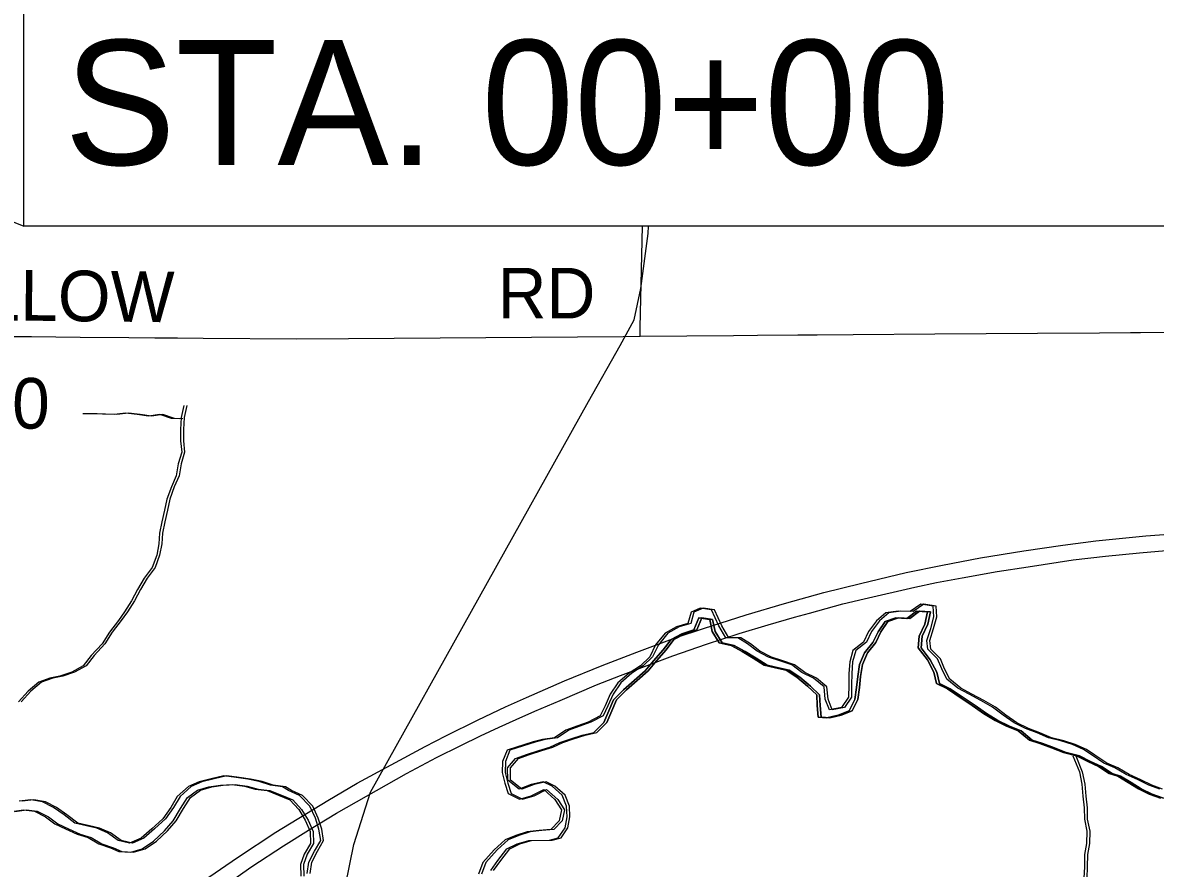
# Model space of a CAD drawing. Extents: x 0 to 34, y 0 to 22.
# Drawn here: x 17.627 to 18.899, y 3.831 to 4.78 of the extents above; entities that cross this region are included whole.
import ezdxf

# ---------------------------------------------------------------- set-up
doc = ezdxf.new("R2010")
doc.units = 0
for name, color, linetype in [('GM_X_County_Road', 7, 'Continuous'), ('GM_X_County_Road_Text', 7, 'Continuous'), ('GM_X_Interstate_Route', 7, 'Continuous'), ('GM_X_Minor_River', 7, 'Continuous'), ('GM_X_Rail_Line', 7, 'Continuous'), ('GM_X_Township_Road', 7, 'Continuous'), ('SH_Text', 7, 'Continuous')]:
    doc.layers.add(name, color=color, linetype=linetype)

msp = doc.modelspace()

# ---------------------------------------------------------------- linework, layer by layer
at = {"layer": 'GM_X_County_Road'}
msp.add_lwpolyline([(17.6039, 4.4277), (17.6373, 4.4274), (17.6921, 4.4268), (17.7464, 4.4263), (17.7757, 4.426), (17.8013, 4.4259), (17.83, 4.4257), (17.935, 4.425), (17.9932, 4.4255), (18.1474, 4.4264), (18.3016, 4.4276), (18.3206, 4.4278), (18.4254, 4.4287), (18.4524, 4.4289), (18.4976, 4.4293), (18.5193, 4.4295), (18.5599, 4.4298), (18.6513, 4.4304), (18.7668, 4.4313), (18.8363, 4.4318), (18.8711, 4.432), (18.8824, 4.4321), (19.0043, 4.433)], dxfattribs=at)
at = {"layer": 'GM_X_Interstate_Route'}
for points in [[(17.8303, 3.8168), (17.8684, 3.8428), (17.9116, 3.8711), (17.9699, 3.9067), (18.0029, 3.9261), (18.0792, 3.9676), (18.1025, 3.9795), (18.1387, 3.9975), (18.1696, 4.012), (18.1932, 4.0225), (18.2357, 4.041), (18.2779, 4.0583), (18.3169, 4.0734), (18.3599, 4.0892), (18.3916, 4.0999), (18.4397, 4.1153), (18.4825, 4.128), (18.5267, 4.1402), (18.568, 4.1504), (18.6194, 4.1627), (18.6599, 4.1711), (18.7026, 4.1791), (18.7512, 4.1872), (18.795, 4.1935), (18.832, 4.1982), (18.8883, 4.2037), (18.9594, 4.209)], [(17.8516, 3.8096), (17.8848, 3.8329), (17.9202, 3.8561), (17.9482, 3.8736), (17.9797, 3.8925), (18.0584, 3.937), (18.092, 3.9549), (18.1194, 3.9686), (18.1413, 3.9794), (18.1622, 3.9892), (18.1815, 3.9977), (18.2023, 4.0072), (18.2309, 4.0192), (18.2715, 4.0365), (18.2984, 4.0471), (18.3313, 4.0593), (18.3572, 4.0691), (18.3952, 4.0822), (18.4317, 4.0941), (18.4644, 4.1039), (18.4937, 4.1126), (18.5106, 4.1171), (18.5483, 4.1274), (18.572, 4.1332), (18.6289, 4.1463), (18.6534, 4.1514), (18.6821, 4.1568), (18.7215, 4.1638), (18.7562, 4.1692), (18.8068, 4.1769), (18.8432, 4.181), (18.8813, 4.1847), (18.9196, 4.1882)]]:
    msp.add_lwpolyline(points, dxfattribs=at)
at = {"layer": 'GM_X_Minor_River'}
for points in [[(17.8083, 4.3502), (17.8055, 4.3365), (17.8045, 4.3232), (17.8047, 4.3103), (17.806, 4.2978), (17.802, 4.2848), (17.7999, 4.2711), (17.7943, 4.2589), (17.7892, 4.2451), (17.7867, 4.2325), (17.7838, 4.2196), (17.781, 4.207), (17.7804, 4.1948), (17.7779, 4.1823), (17.7727, 4.1685), (17.7638, 4.1563), (17.7564, 4.1436), (17.7497, 4.131), (17.7419, 4.1187), (17.7348, 4.1088), (17.7247, 4.0957), (17.7166, 4.0827), (17.7042, 4.0696), (17.6953, 4.0581), (17.6825, 4.0507), (17.6692, 4.0464), (17.6579, 4.044), (17.6454, 4.0396), (17.6334, 4.0296), (17.6226, 4.0177)], [(17.8116, 4.3502), (17.8087, 4.3365), (17.8078, 4.3232), (17.8079, 4.3103), (17.8092, 4.2978), (17.8052, 4.2848), (17.8031, 4.2711), (17.7976, 4.2589), (17.7925, 4.2451), (17.79, 4.2325), (17.7871, 4.2196), (17.7842, 4.207), (17.7836, 4.1948), (17.7811, 4.1823), (17.776, 4.1685), (17.767, 4.1563), (17.7596, 4.1436), (17.753, 4.131), (17.7452, 4.1187), (17.7381, 4.1088), (17.728, 4.0957), (17.7198, 4.0827), (17.7075, 4.0696), (17.6985, 4.0581), (17.6857, 4.0507), (17.6725, 4.0464), (17.6612, 4.044), (17.6487, 4.0396), (17.6367, 4.0296), (17.6259, 4.0177)], [(17.804, 4.3353), (17.7945, 4.3356), (17.7815, 4.34), (17.7687, 4.3383), (17.7561, 4.3401), (17.7429, 4.3414), (17.73, 4.3401), (17.7171, 4.3403), (17.7076, 4.3406), (17.6951, 4.3408)], [(17.8072, 4.3353), (17.7978, 4.3356), (17.7848, 4.34), (17.7719, 4.3383), (17.7594, 4.3401), (17.7461, 4.3414), (17.7332, 4.3401), (17.7203, 4.3403), (17.7109, 4.3406), (17.6984, 4.3408)], [(18.9039, 3.9194), (18.8917, 3.9242), (18.8795, 3.9301), (18.8661, 3.936), (18.8535, 3.9435), (18.8413, 3.9486), (18.8279, 3.9576), (18.8184, 3.9639), (18.8058, 3.9695), (18.7928, 3.9738), (18.7791, 3.9771), (18.7662, 3.9826), (18.7532, 3.9878), (18.7403, 3.9941), (18.728, 4.0026), (18.7161, 4.0116), (18.7032, 4.019), (18.6898, 4.0261), (18.6772, 4.0328), (18.6649, 4.0429), (18.6591, 4.0546), (18.6544, 4.0659), (18.6437, 4.0768), (18.6424, 4.0863), (18.6468, 4.1), (18.6504, 4.113), (18.6495, 4.1251), (18.6358, 4.1272), (18.6238, 4.1191), (18.6101, 4.1193), (18.5965, 4.1176), (18.586, 4.1083), (18.5771, 4.0964), (18.5715, 4.0846), (18.5595, 4.0753), (18.5559, 4.0624), (18.5549, 4.0494), (18.5547, 4.0365), (18.5545, 4.0228), (18.5467, 4.0113), (18.5331, 4.0085), (18.5283, 4.0206), (18.527, 4.0343), (18.5152, 4.044), (18.5022, 4.0503), (18.4907, 4.0592), (18.4774, 4.0636), (18.4648, 4.0676), (18.4518, 4.0743), (18.4411, 4.0825), (18.4304, 4.0892), (18.4168, 4.0894), (18.409, 4.103), (18.4008, 4.1208), (18.3879, 4.1225), (18.3777, 4.1182), (18.3741, 4.1056), (18.3613, 4.1016), (18.3485, 4.0946), (18.338, 4.0816), (18.3313, 4.0682), (18.3209, 4.0578), (18.3081, 4.0497), (18.2957, 4.0389)], [(18.9039, 3.9194), (18.8917, 3.9242), (18.8795, 3.9301), (18.8661, 3.936), (18.8535, 3.9435), (18.8413, 3.9486), (18.8279, 3.9576), (18.8184, 3.9639), (18.8058, 3.9695), (18.7928, 3.9738), (18.7791, 3.9771), (18.7662, 3.9826), (18.7532, 3.9878), (18.7403, 3.9941), (18.728, 4.0026), (18.7161, 4.0116), (18.7032, 4.019), (18.6898, 4.0261), (18.6772, 4.0328), (18.6649, 4.0429), (18.6591, 4.0546), (18.6544, 4.0659), (18.6437, 4.0768), (18.6424, 4.0863), (18.6468, 4.1), (18.6504, 4.113), (18.6495, 4.1251), (18.6358, 4.1272), (18.6238, 4.1191), (18.6101, 4.1193), (18.5965, 4.1176), (18.586, 4.1083), (18.5771, 4.0964), (18.5715, 4.0846), (18.5595, 4.0753), (18.5559, 4.0624), (18.5549, 4.0494), (18.5547, 4.0365), (18.5545, 4.0228), (18.5467, 4.0113), (18.5331, 4.0085), (18.5283, 4.0206), (18.527, 4.0343), (18.5152, 4.044), (18.5022, 4.0503), (18.4907, 4.0592), (18.4774, 4.0636), (18.4648, 4.0676), (18.4518, 4.0743), (18.4411, 4.0825), (18.4304, 4.0892), (18.4168, 4.0894), (18.409, 4.103), (18.4008, 4.1208), (18.3879, 4.1225), (18.3777, 4.1182), (18.3741, 4.1056), (18.3613, 4.1016), (18.3485, 4.0946), (18.338, 4.0816), (18.3313, 4.0682), (18.3209, 4.0578), (18.3081, 4.0497), (18.2957, 4.0389)], [(18.9071, 3.9194), (18.8949, 3.9242), (18.8827, 3.9301), (18.8694, 3.936), (18.8568, 3.9435), (18.8446, 3.9486), (18.8312, 3.9576), (18.8216, 3.9639), (18.809, 3.9695), (18.7961, 3.9738), (18.7824, 3.9771), (18.7694, 3.9826), (18.7565, 3.9878), (18.7435, 3.9941), (18.7313, 4.0026), (18.7194, 4.0116), (18.7064, 4.019), (18.6931, 4.0261), (18.6805, 4.0328), (18.6682, 4.0429), (18.6624, 4.0546), (18.6577, 4.0659), (18.6469, 4.0768), (18.6457, 4.0863), (18.65, 4.1), (18.6537, 4.113), (18.6528, 4.1251), (18.6391, 4.1272), (18.6271, 4.1191), (18.6134, 4.1193), (18.5998, 4.1176), (18.5893, 4.1083), (18.5803, 4.0964), (18.5748, 4.0846), (18.5628, 4.0753), (18.5591, 4.0624), (18.5582, 4.0494), (18.558, 4.0365), (18.5578, 4.0228), (18.5499, 4.0113), (18.5363, 4.0085), (18.5316, 4.0206), (18.5303, 4.0343), (18.5184, 4.044), (18.5055, 4.0503), (18.494, 4.0592), (18.4806, 4.0636), (18.4681, 4.0676), (18.4551, 4.0743), (18.4444, 4.0825), (18.4337, 4.0892), (18.42, 4.0894), (18.4123, 4.103), (18.4041, 4.1208), (18.3912, 4.1225), (18.381, 4.1182), (18.3774, 4.1056), (18.3645, 4.1016), (18.3517, 4.0946), (18.3413, 4.0816), (18.3346, 4.0682), (18.3241, 4.0578), (18.3113, 4.0497), (18.299, 4.0389)], [(18.9071, 3.9194), (18.8949, 3.9242), (18.8827, 3.9301), (18.8694, 3.936), (18.8568, 3.9435), (18.8446, 3.9486), (18.8312, 3.9576), (18.8216, 3.9639), (18.809, 3.9695), (18.7961, 3.9738), (18.7824, 3.9771), (18.7694, 3.9826), (18.7565, 3.9878), (18.7435, 3.9941), (18.7313, 4.0026), (18.7194, 4.0116), (18.7064, 4.019), (18.6931, 4.0261), (18.6805, 4.0328), (18.6682, 4.0429), (18.6624, 4.0546), (18.6577, 4.0659), (18.6469, 4.0768), (18.6457, 4.0863), (18.65, 4.1), (18.6537, 4.113), (18.6528, 4.1251), (18.6391, 4.1272), (18.6271, 4.1191), (18.6134, 4.1193), (18.5998, 4.1176), (18.5893, 4.1083), (18.5803, 4.0964), (18.5748, 4.0846), (18.5628, 4.0753), (18.5591, 4.0624), (18.5582, 4.0494), (18.558, 4.0365), (18.5578, 4.0228), (18.5499, 4.0113), (18.5363, 4.0085), (18.5316, 4.0206), (18.5303, 4.0343), (18.5184, 4.044), (18.5055, 4.0503), (18.494, 4.0592), (18.4806, 4.0636), (18.4681, 4.0676), (18.4551, 4.0743), (18.4444, 4.0825), (18.4337, 4.0892), (18.42, 4.0894), (18.4123, 4.103), (18.4041, 4.1208), (18.3912, 4.1225), (18.381, 4.1182), (18.3774, 4.1056), (18.3645, 4.1016), (18.3517, 4.0946), (18.3413, 4.0816), (18.3346, 4.0682), (18.3241, 4.0578), (18.3113, 4.0497), (18.299, 4.0389)], [(18.28, 3.9942), (18.2855, 4.0076), (18.2906, 4.0198), (18.3019, 4.031), (18.3139, 4.0414), (18.3262, 4.0522), (18.3356, 4.0637), (18.3464, 4.076), (18.3554, 4.0875), (18.3674, 4.0937), (18.381, 4.0985), (18.3865, 4.1118), (18.3987, 4.1101), (18.4015, 4.0965), (18.4093, 4.0836), (18.4229, 4.0808), (18.4352, 4.0741), (18.4474, 4.0667), (18.46, 4.0588), (18.4726, 4.0556), (18.4847, 4.0531), (18.4966, 4.0453), (18.5084, 4.0352), (18.5188, 4.0254), (18.5193, 4.0133), (18.5206, 4.0004), (18.5301, 3.9997), (18.543, 4.0025), (18.5554, 4.0073), (18.5617, 4.0203), (18.5634, 4.0336), (18.5648, 4.0461), (18.5669, 4.0595), (18.5724, 4.0725), (18.5818, 4.084), (18.5877, 4.0962), (18.5955, 4.1077), (18.6076, 4.112), (18.6201, 4.1111), (18.631, 4.1192), (18.6431, 4.1186), (18.6403, 4.1049), (18.634, 4.0911), (18.6326, 4.0782), (18.6431, 4.0646), (18.6504, 4.0507), (18.6532, 4.0382), (18.6655, 4.0322), (18.6811, 4.0218), (18.6934, 4.0136), (18.706, 4.0046), (18.719, 3.9965), (18.732, 3.9902), (18.7449, 3.985), (18.7576, 3.9745), (18.7694, 3.9709), (18.7823, 3.9661), (18.7957, 3.9606), (18.8105, 3.957), (18.8231, 3.9507), (18.8353, 3.9448), (18.8471, 3.9373), (18.8567, 3.934), (18.8685, 3.9269), (18.88, 3.9199), (18.8922, 3.914), (18.9047, 3.9096)], [(18.9047, 3.9096), (18.8922, 3.914), (18.88, 3.9199), (18.8685, 3.9269), (18.8567, 3.934), (18.8471, 3.9373), (18.8353, 3.9448), (18.8231, 3.9507), (18.8105, 3.957), (18.7957, 3.9606), (18.7823, 3.9661), (18.7694, 3.9709), (18.7576, 3.9745), (18.7449, 3.985), (18.732, 3.9902), (18.719, 3.9965), (18.706, 4.0046), (18.6934, 4.0136), (18.6811, 4.0218), (18.6655, 4.0322), (18.6532, 4.0382), (18.6504, 4.0507), (18.6431, 4.0646), (18.6326, 4.0782), (18.634, 4.0911), (18.6403, 4.1049), (18.6431, 4.1186), (18.631, 4.1192), (18.6201, 4.1111), (18.6076, 4.112), (18.5955, 4.1077), (18.5877, 4.0962), (18.5818, 4.084), (18.5724, 4.0725), (18.5669, 4.0595), (18.5648, 4.0461), (18.5634, 4.0336), (18.5617, 4.0203), (18.5554, 4.0073), (18.543, 4.0025), (18.5301, 3.9997), (18.5206, 4.0004), (18.5193, 4.0133), (18.5188, 4.0254), (18.5084, 4.0352), (18.4966, 4.0453), (18.4847, 4.0531), (18.4726, 4.0556), (18.46, 4.0588), (18.4474, 4.0667), (18.4352, 4.0741), (18.4229, 4.0808), (18.4093, 4.0836), (18.4015, 4.0965), (18.3987, 4.1101), (18.3865, 4.1118), (18.381, 4.0985), (18.3674, 4.0937), (18.3554, 4.0875), (18.3464, 4.076), (18.3356, 4.0637), (18.3262, 4.0522), (18.3139, 4.0414), (18.3019, 4.031), (18.2906, 4.0198), (18.2855, 4.0076), (18.28, 3.9942)], [(18.2832, 3.9942), (18.2887, 4.0076), (18.2939, 4.0198), (18.3051, 4.031), (18.3171, 4.0414), (18.3295, 4.0522), (18.3388, 4.0637), (18.3497, 4.076), (18.3586, 4.0875), (18.3707, 4.0937), (18.3843, 4.0985), (18.3898, 4.1118), (18.4019, 4.1101), (18.4048, 4.0965), (18.4125, 4.0836), (18.4262, 4.0808), (18.4384, 4.0741), (18.4507, 4.0667), (18.4633, 4.0588), (18.4758, 4.0556), (18.488, 4.0531), (18.4998, 4.0453), (18.5117, 4.0352), (18.5221, 4.0254), (18.5226, 4.0133), (18.5239, 4.0004), (18.5334, 3.9997), (18.5463, 4.0025), (18.5587, 4.0073), (18.565, 4.0203), (18.5667, 4.0336), (18.5681, 4.0461), (18.5702, 4.0595), (18.5757, 4.0725), (18.585, 4.084), (18.5909, 4.0962), (18.5988, 4.1077), (18.6108, 4.112), (18.6234, 4.1111), (18.6343, 4.1192), (18.6464, 4.1186), (18.6435, 4.1049), (18.6373, 4.0911), (18.6359, 4.0782), (18.6463, 4.0646), (18.6537, 4.0507), (18.6565, 4.0382), (18.6687, 4.0322), (18.6844, 4.0218), (18.6966, 4.0136), (18.7093, 4.0046), (18.7223, 3.9965), (18.7352, 3.9902), (18.7482, 3.985), (18.7608, 3.9745), (18.7726, 3.9709), (18.7856, 3.9661), (18.7989, 3.9606), (18.8138, 3.957), (18.8263, 3.9507), (18.8386, 3.9448), (18.8504, 3.9373), (18.8599, 3.934), (18.8718, 3.9269), (18.8832, 3.9199), (18.8954, 3.914), (18.908, 3.9096)], [(18.908, 3.9096), (18.8954, 3.914), (18.8832, 3.9199), (18.8718, 3.9269), (18.8599, 3.934), (18.8504, 3.9373), (18.8386, 3.9448), (18.8263, 3.9507), (18.8138, 3.957), (18.7989, 3.9606), (18.7856, 3.9661), (18.7726, 3.9709), (18.7608, 3.9745), (18.7482, 3.985), (18.7352, 3.9902), (18.7223, 3.9965), (18.7093, 4.0046), (18.6966, 4.0136), (18.6844, 4.0218), (18.6687, 4.0322), (18.6565, 4.0382), (18.6537, 4.0507), (18.6463, 4.0646), (18.6359, 4.0782), (18.6373, 4.0911), (18.6435, 4.1049), (18.6464, 4.1186), (18.6343, 4.1192), (18.6234, 4.1111), (18.6108, 4.112), (18.5988, 4.1077), (18.5909, 4.0962), (18.585, 4.084), (18.5757, 4.0725), (18.5702, 4.0595), (18.5681, 4.0461), (18.5667, 4.0336), (18.565, 4.0203), (18.5587, 4.0073), (18.5463, 4.0025), (18.5334, 3.9997), (18.5239, 4.0004), (18.5226, 4.0133), (18.5221, 4.0254), (18.5117, 4.0352), (18.4998, 4.0453), (18.488, 4.0531), (18.4758, 4.0556), (18.4633, 4.0588), (18.4507, 4.0667), (18.4384, 4.0741), (18.4262, 4.0808), (18.4125, 4.0836), (18.4048, 4.0965), (18.4019, 4.1101), (18.3898, 4.1118), (18.3843, 4.0985), (18.3707, 4.0937), (18.3586, 4.0875), (18.3497, 4.076), (18.3388, 4.0637), (18.3295, 4.0522), (18.3171, 4.0414), (18.3051, 4.031), (18.2939, 4.0198), (18.2887, 4.0076), (18.2832, 3.9942)], [(18.2957, 4.0389), (18.2871, 4.0262), (18.2812, 4.0132), (18.2757, 4.0018), (18.2621, 3.9947), (18.2497, 3.9904), (18.2372, 3.9857), (18.2244, 3.9772), (18.2108, 3.9751), (18.2006, 3.9727), (18.1712, 3.9632), (18.166, 3.9506), (18.1658, 3.9384), (18.1686, 3.9263), (18.1725, 3.9146), (18.1851, 3.9083), (18.1983, 3.9122), (18.2123, 3.9193), (18.2249, 3.908), (18.2323, 3.8963), (18.2298, 3.8841), (18.2204, 3.8741), (18.2072, 3.8732), (18.1939, 3.8715), (18.1811, 3.8676), (18.169, 3.8625), (18.1567, 3.8513), (18.1439, 3.8371), (18.1392, 3.8241)], [(18.299, 4.0389), (18.2904, 4.0262), (18.2845, 4.0132), (18.279, 4.0018), (18.2654, 3.9947), (18.2529, 3.9904), (18.2405, 3.9857), (18.2277, 3.9772), (18.2141, 3.9751), (18.2039, 3.9727), (18.1744, 3.9632), (18.1693, 3.9506), (18.1691, 3.9384), (18.1719, 3.9263), (18.1758, 3.9146), (18.1884, 3.9083), (18.2016, 3.9122), (18.2156, 3.9193), (18.2282, 3.908), (18.2356, 3.8963), (18.2331, 3.8841), (18.2237, 3.8741), (18.2104, 3.8732), (18.1972, 3.8715), (18.1844, 3.8676), (18.1723, 3.8625), (18.1599, 3.8513), (18.1472, 3.8371), (18.1424, 3.8241)], [(18.1528, 3.8281), (18.161, 3.8396), (18.171, 3.8526), (18.1824, 3.8581), (18.1956, 3.862), (18.2187, 3.8623), (18.2285, 3.8651), (18.2363, 3.8763), (18.2385, 3.8884), (18.2379, 3.9006), (18.2332, 3.9127), (18.2217, 3.9228), (18.2118, 3.9276), (18.1982, 3.9248), (18.1846, 3.9197), (18.172, 3.9298), (18.1718, 3.9434), (18.1808, 3.9538), (18.1932, 3.9585), (18.2068, 3.9629), (18.2193, 3.9665), (18.2306, 3.9719), (18.2427, 3.9759), (18.2555, 3.9802), (18.2687, 3.9831), (18.28, 3.9942)], [(18.156, 3.8281), (18.1642, 3.8396), (18.1743, 3.8526), (18.1856, 3.8581), (18.1988, 3.862), (18.222, 3.8623), (18.2318, 3.8651), (18.2396, 3.8763), (18.2417, 3.8884), (18.2412, 3.9006), (18.2365, 3.9127), (18.225, 3.9228), (18.2151, 3.9276), (18.2015, 3.9248), (18.1879, 3.9197), (18.1752, 3.9298), (18.1751, 3.9434), (18.184, 3.9538), (18.1965, 3.9585), (18.2101, 3.9629), (18.2225, 3.9665), (18.2338, 3.9719), (18.2459, 3.9759), (18.2588, 3.9802), (18.272, 3.9831), (18.2832, 3.9942)], [(18.8064, 3.957), (18.8138, 3.9388), (18.8166, 3.9251), (18.8175, 3.9115), (18.8192, 3.8986), (18.8193, 3.886), (18.8222, 3.8724), (18.8216, 3.8587), (18.8195, 3.8462), (18.8193, 3.8325), (18.8187, 3.8195), (18.82, 3.8059), (18.8205, 3.7926), (18.8226, 3.7789), (18.8262, 3.7657), (18.8298, 3.7517), (18.8349, 3.7381), (18.8335, 3.7248), (18.8346, 3.7025)], [(18.8097, 3.957), (18.817, 3.9388), (18.8198, 3.9251), (18.8208, 3.9115), (18.8225, 3.8986), (18.8226, 3.886), (18.8254, 3.8724), (18.8249, 3.8587), (18.8227, 3.8462), (18.8225, 3.8325), (18.8219, 3.8195), (18.8233, 3.8059), (18.8238, 3.7926), (18.8259, 3.7789), (18.8295, 3.7657), (18.833, 3.7517), (18.8381, 3.7381), (18.8368, 3.7248), (18.8379, 3.7025)], [(17.9469, 3.825), (17.9487, 3.8376), (17.955, 3.8498), (17.962, 3.8621), (17.96, 3.8746), (17.956, 3.8871), (17.9498, 3.9003), (17.9382, 3.9123), (17.926, 3.9182), (17.9192, 3.9223), (17.9055, 3.924), (17.8929, 3.9281), (17.88, 3.9309), (17.8671, 3.9327), (17.8534, 3.9344), (17.8391, 3.9312), (17.8254, 3.9279), (17.8134, 3.9225), (17.801, 3.9113), (17.7936, 3.899), (17.7846, 3.8864), (17.7723, 3.8752), (17.7603, 3.8644), (17.7475, 3.8589), (17.7345, 3.8618), (17.7227, 3.8704), (17.7105, 3.8759), (17.6991, 3.8784), (17.6861, 3.8813), (17.6739, 3.8907), (17.662, 3.8989), (17.6498, 3.9055), (17.6365, 3.9077), (17.6236, 3.906)], [(17.9502, 3.825), (17.9519, 3.8376), (17.9582, 3.8498), (17.9653, 3.8621), (17.9632, 3.8746), (17.9593, 3.8871), (17.953, 3.9003), (17.9415, 3.9123), (17.9293, 3.9182), (17.9224, 3.9223), (17.9088, 3.924), (17.8962, 3.9281), (17.8833, 3.9309), (17.8704, 3.9327), (17.8567, 3.9344), (17.8423, 3.9312), (17.8287, 3.9279), (17.8166, 3.9225), (17.8043, 3.9113), (17.7968, 3.899), (17.7879, 3.8864), (17.7755, 3.8752), (17.7635, 3.8644), (17.7507, 3.8589), (17.7378, 3.8618), (17.7259, 3.8704), (17.7137, 3.8759), (17.7023, 3.8784), (17.6894, 3.8813), (17.6771, 3.8907), (17.6653, 3.8989), (17.6531, 3.9055), (17.6398, 3.9077), (17.6269, 3.906)], [(17.6154, 3.8945), (17.6283, 3.8962), (17.6405, 3.8948), (17.6531, 3.8885), (17.6634, 3.8806), (17.6756, 3.8751), (17.6886, 3.8692), (17.7011, 3.8652), (17.713, 3.8581), (17.7259, 3.8537), (17.7354, 3.8497), (17.7487, 3.8487), (17.7616, 3.8527), (17.7743, 3.8612), (17.7867, 3.8727), (17.7964, 3.8839), (17.8046, 3.8977), (17.8124, 3.9103), (17.8237, 3.9184), (17.8365, 3.922), (17.8494, 3.9241), (17.8626, 3.9246), (17.8763, 3.9229), (17.8885, 3.9196), (17.9018, 3.9179), (17.9147, 3.9128), (17.9273, 3.9076), (17.9373, 3.8967), (17.9447, 3.8847), (17.9501, 3.8722), (17.9507, 3.8585), (17.9436, 3.8466), (17.9392, 3.8348), (17.9398, 3.8219)], [(17.6187, 3.8945), (17.6316, 3.8962), (17.6437, 3.8948), (17.6563, 3.8885), (17.6667, 3.8806), (17.6789, 3.8751), (17.6918, 3.8692), (17.7044, 3.8652), (17.7162, 3.8581), (17.7292, 3.8537), (17.7387, 3.8497), (17.752, 3.8487), (17.7648, 3.8527), (17.7776, 3.8612), (17.79, 3.8727), (17.7997, 3.8839), (17.8079, 3.8977), (17.8157, 3.9103), (17.8269, 3.9184), (17.8398, 3.922), (17.8526, 3.9241), (17.8659, 3.9246), (17.8796, 3.9229), (17.8918, 3.9196), (17.905, 3.9179), (17.918, 3.9128), (17.9306, 3.9076), (17.9406, 3.8967), (17.9479, 3.8847), (17.9534, 3.8722), (17.954, 3.8585), (17.9469, 3.8466), (17.9425, 3.8348), (17.943, 3.8219)]]:
    msp.add_lwpolyline(points, dxfattribs=at)
at = {"layer": 'GM_X_Rail_Line'}
msp.add_lwpolyline([(17.9817, 3.727), (17.9899, 3.8116), (17.9993, 3.8573), (18.018, 3.9161), (18.2628, 4.3545), (18.2981, 4.4174), (18.3137, 4.4462), (18.3213, 4.4815), (18.3297, 4.5431), (18.33, 4.5513)], dxfattribs=at)
at = {"layer": 'GM_X_Township_Road'}
msp.add_lwpolyline([(18.3206, 4.4278), (18.3207, 4.4375), (18.3232, 4.5513)], dxfattribs=at)
at = {"layer": 'SH_Text'}
for points in [[(17.6287, 5.2416), (16.4069, 5.0452), (17.6287, 4.5513)], [(17.6287, 5.2416), (19.3492, 5.2416), (19.3492, 4.5513), (17.6287, 4.5513)]]:
    msp.add_lwpolyline(points, close=True, dxfattribs=at)

# ---------------------------------------------------------------- texts
at = {"layer": 'GM_X_County_Road_Text'}
for s, rotation, p in [('WILLOW', 359.3425, (17.4893, 4.447)), ('RD', 0, (18.1606, 4.4478)), ('C-90', 359.3129, (17.4928, 4.3259))]:
    msp.add_text(s, height=0.05682, rotation=rotation, dxfattribs=at).set_placement(p)
at = {"layer": 'SH_Text'}
msp.add_text('STA. 00+00', height=0.14, dxfattribs=at).set_placement((17.6742, 4.6202))

doc.saveas('drawing.dxf')
